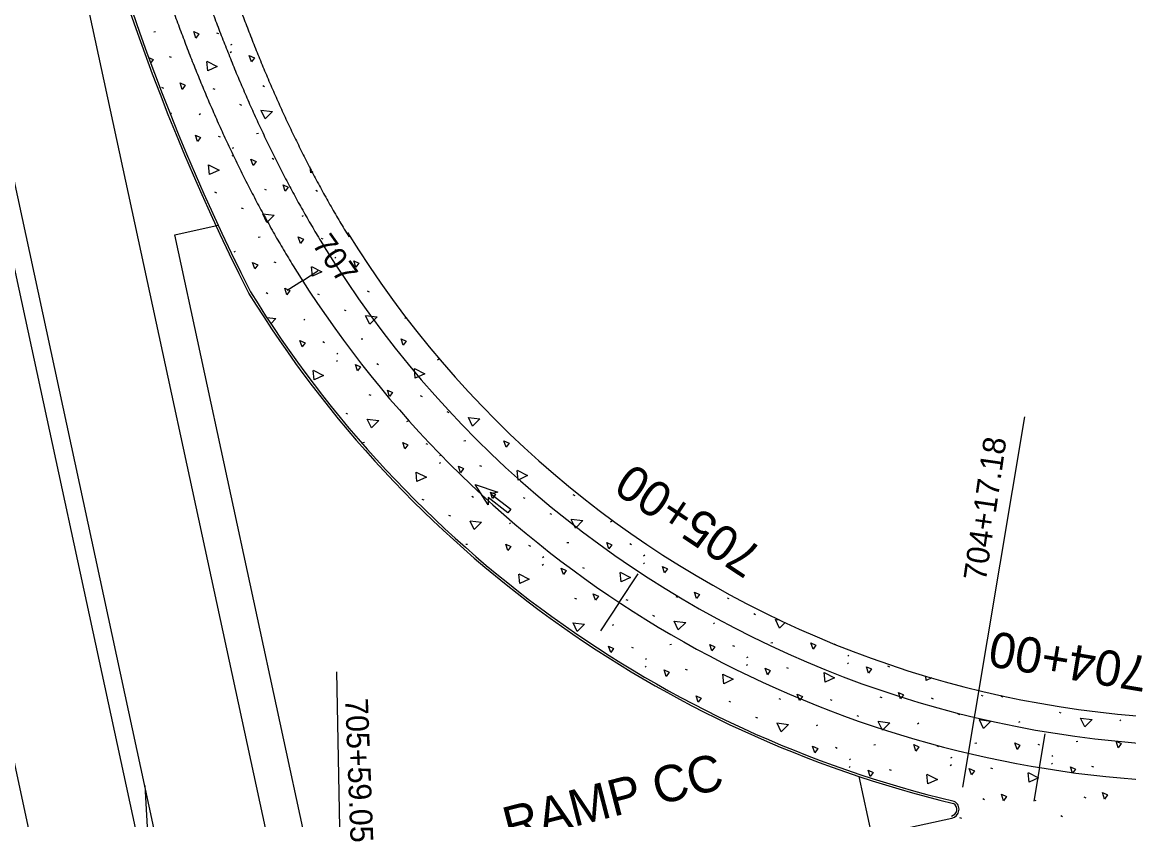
# Model space of a CAD drawing. Extents: x 0 to 1360, y 0 to 880.
# Drawn here: x 166 to 409.3, y 135 to 310.5 of the extents above; entities that cross this region are included whole.
import ezdxf

# ---------------------------------------------------------------- set-up
doc = ezdxf.new("R2010")
doc.units = 0
for name, color, linetype in [('Default', 7, 'Continuous'), ('PM_P_Cells', 7, 'Continuous'), ('PV_X_Curb', 7, 'Continuous'), ('RD_X_Concrete_Pad', 7, 'Continuous'), ('SH_Text', 7, 'Continuous')]:
    doc.layers.add(name, color=color, linetype=linetype)

# ---------------------------------------------------------------- blocks, each defined once
blk = doc.blocks.new('PMTHRP')
at = {"layer": 'PM_P_Cells'}
for p, q in [((-9.5, -0.5), (-9.5, 0.5)), ((-9.5, 0.5), (-4, 0.5)), ((-9.5, 0), (-9.5, 0)), ((-4, 0.5), (-5, 1.74)), ((-5, 1.74), (0, 0)), ((0, 0), (-5, -1.74)), ((0, 0), (0, 0)), ((-4, -0.5), (-9.5, -0.5)), ((-5, -1.74), (-4, -0.5))]:
    blk.add_line(p, q, dxfattribs=at)

msp = doc.modelspace()

# ---------------------------------------------------------------- linework, layer by layer
at = {"layer": 'Default'}
for p, q in [((243.77, 21.21), (123.28, 579.31)), ((219.22, 21.21), (123.28, 465.59)), ((215.13, 21.21), (123.28, 446.64)), ((195.36, 308.37), (194.96, 308.32)), ((208.78, 308.18), (209.18, 308.01)), ((212.11, 305.61), (211.85, 305.43)), ((198.38, 302.96), (198.79, 302.79)), ((212.04, 303.94), (211.77, 303.75)), ((196.67, 296.18), (197.08, 296.01)), ((207.96, 295.92), (208.36, 295.75)), ((218.91, 296.54), (219.31, 296.37)), ((213.83, 292.42), (214.23, 292.25)), ((205.21, 290.32), (204.94, 290.14)), ((209.15, 285.41), (209.55, 285.24)), ((217.97, 285.97), (217.57, 285.92)), ((212.48, 282.85), (212.22, 282.67)), ((212.41, 281.17), (212.15, 280.99)), ((220.99, 280.55), (221.39, 280.38)), ((208.33, 273.15), (208.73, 272.98)), ((219.28, 273.78), (219.68, 273.61)), ((230.57, 273.52), (230.97, 273.34)), ((214.2, 269.65), (214.6, 269.48)), ((227.81, 267.92), (227.55, 267.74)), ((199.59, 263.75), (209.14, 265.81)), ((231.46, 116.15), (199.59, 263.75)), ((218.34, 263.2), (217.94, 263.15)), ((231.76, 263.01), (232.16, 262.84)), ((235.09, 260.45), (234.83, 260.26)), ((212.85, 260.08), (212.59, 259.9)), ((212.78, 258.4), (212.69, 258.34)), ((235.02, 258.77), (234.75, 258.58)), ((221.36, 257.79), (221.77, 257.62)), ((225.61, 256.92), (225.61, 256.92)), ((227.67, 253.63), (231.04, 255.78)), ((227.67, 253.63), (224.29, 251.48)), ((219.65, 251.01), (220.06, 250.84)), ((230.94, 250.75), (231.34, 250.58)), ((241.89, 251.37), (242.29, 251.2)), ((236.81, 247.25), (237.21, 247.08)), ((228.19, 245.15), (227.92, 244.97)), ((250.41, 245.51), (250.16, 245.34)), ((232.13, 240.25), (232.53, 240.07)), ((240.95, 240.8), (240.55, 240.75)), ((235.39, 236), (235.13, 235.82)), ((235.46, 237.68), (235.2, 237.5)), ((257.63, 236.36), (257.36, 236.18)), ((243.97, 235.38), (244.37, 235.21)), ((242.26, 228.61), (242.66, 228.44)), ((253.55, 228.35), (253.95, 228.18)), ((237.18, 224.48), (237.58, 224.31)), ((259.42, 224.85), (259.82, 224.67)), ((250.79, 222.75), (250.53, 222.57)), ((372.82, 142.26), (386.4, 223.65)), ((241.32, 218.03), (240.92, 217.98)), ((254.74, 217.84), (255.14, 217.67)), ((263.56, 218.4), (263.16, 218.35)), ((258.07, 215.28), (257.81, 215.09)), ((258, 213.6), (257.73, 213.41)), ((266.58, 212.98), (266.98, 212.81)), ((253.92, 205.58), (254.32, 205.41)), ((264.87, 206.2), (265.27, 206.03)), ((276.15, 205.94), (276.56, 205.77)), ((287.11, 206.57), (287.51, 206.39)), ((259.79, 202.08), (260.19, 201.91)), ((282.02, 202.44), (282.43, 202.27)), ((273.4, 200.35), (273.14, 200.17)), ((295.64, 200.71), (295.38, 200.53)), ((263.93, 195.63), (263.53, 195.58)), ((277.35, 195.44), (277.75, 195.27)), ((286.17, 195.99), (285.77, 195.94)), ((299.58, 195.8), (299.99, 195.63)), ((280.68, 192.87), (280.42, 192.69)), ((302.92, 193.23), (302.65, 193.05)), ((280.61, 191.19), (280.34, 191.01)), ((289.19, 190.58), (289.59, 190.41)), ((302.84, 191.56), (302.58, 191.37)), ((155.32, 189.22), (171.25, 115.43)), ((297.28, 182.86), (301.42, 189.12)), ((287.48, 183.8), (287.88, 183.63)), ((297.28, 182.86), (293.15, 176.61)), ((298.76, 183.54), (299.17, 183.37)), ((309.72, 184.16), (310.12, 183.99)), ((321, 183.9), (321.4, 183.73)), ((304.63, 180.04), (305.04, 179.87)), ((326.87, 180.4), (327.27, 180.23)), ((282.8, 179.51), (282.8, 179.51)), ((296.01, 177.94), (295.75, 177.76)), ((318.25, 178.31), (317.99, 178.12)), ((299.96, 173.04), (300.36, 172.86)), ((308.77, 173.59), (308.38, 173.54)), ((322.19, 173.4), (322.6, 173.23)), ((331.01, 173.95), (330.61, 173.9)), ((344.43, 173.76), (344.83, 173.59)), ((303.29, 170.47), (303.03, 170.29)), ((325.53, 170.83), (325.26, 170.65)), ((347.76, 171.19), (347.5, 171.01)), ((303.22, 168.79), (302.95, 168.61)), ((311.8, 168.17), (312.2, 168)), ((325.45, 169.15), (325.19, 168.97)), ((334.04, 168.54), (334.44, 168.37)), ((347.69, 169.51), (347.43, 169.33)), ((356.27, 168.9), (356.68, 168.73)), ((236.63, 92.19), (235.19, 167.58)), ((321.37, 161.14), (321.77, 160.97)), ((332.33, 161.76), (332.73, 161.59)), ((343.61, 161.5), (344.01, 161.33)), ((354.56, 162.12), (354.97, 161.95)), ((365.85, 161.86), (366.25, 161.69)), ((376.8, 162.48), (377.2, 162.31)), ((371.72, 158.36), (372.12, 158.19)), ((393.96, 158.72), (394.36, 158.55)), ((327.24, 157.64), (327.64, 157.46)), ((340.86, 155.9), (340.6, 155.72)), ((349.48, 158), (349.88, 157.83)), ((363.1, 156.27), (362.83, 156.08)), ((385.33, 156.63), (385.07, 156.45)), ((407.57, 156.99), (407.31, 156.81)), ((389.66, 146.53), (390.9, 153.93)), ((344.8, 150.99), (345.2, 150.82)), ((353.62, 151.55), (353.22, 151.5)), ((367.04, 151.36), (367.44, 151.19)), ((375.86, 151.91), (375.46, 151.86)), ((389.28, 151.72), (389.68, 151.55)), ((398.1, 152.27), (397.7, 152.22)), ((348.14, 148.43), (347.87, 148.25)), ((370.37, 148.79), (370.11, 148.61)), ((392.61, 149.15), (392.35, 148.97)), ((348.06, 146.75), (347.8, 146.57)), ((356.64, 146.13), (357.05, 145.96)), ((370.3, 147.11), (370.04, 146.93)), ((378.88, 146.5), (379.29, 146.32)), ((389.66, 146.53), (388.43, 139.13)), ((392.54, 147.47), (392.27, 147.29)), ((401.12, 146.86), (401.52, 146.69)), ((352.85, 131.38), (350, 144.55)), ((193, 142.63), (195.85, 91.07)), ((377.17, 139.72), (377.57, 139.55)), ((388.46, 139.46), (388.86, 139.29)), ((399.41, 140.08), (399.81, 139.91)), ((372.09, 135.59), (372.49, 135.42)), ((394.33, 135.96), (394.73, 135.79))]:
    msp.add_line(p, q, dxfattribs=at)
for points in [[(203.76, 308.41), (204.88, 307.89), (204.22, 307), (203.76, 308.41)], [(193.82, 302.75), (194.84, 302.28), (194.28, 301.5)], [(206.66, 301.89), (208.94, 300.73), (206.87, 299.77), (206.66, 301.85)], [(215.96, 303.15), (217.08, 302.64), (216.43, 301.74), (215.96, 303.15)], [(200.77, 297.13), (201.89, 296.61), (201.23, 295.71), (200.77, 297.13)], [(198.51, 290.5), (198.85, 290.46), (198.62, 290.23)], [(218.54, 291.13), (221.08, 290.82), (219.47, 289.21), (218.56, 291.09)], [(204.13, 285.64), (205.25, 285.13), (204.59, 284.23), (204.13, 285.64)], [(216.33, 280.39), (217.45, 279.87), (216.8, 278.98), (216.33, 280.39)], [(207.03, 279.13), (209.32, 277.97), (207.24, 277), (207.03, 279.08)], [(229.93, 277.57), (229.48, 277.36), (229.35, 278.68)], [(223.38, 274.72), (224.49, 274.21), (223.84, 273.31), (223.38, 274.72)], [(218.91, 268.37), (221.45, 268.06), (219.84, 266.44), (218.93, 268.33)], [(226.74, 263.24), (227.86, 262.73), (227.2, 261.83), (226.74, 263.24)], [(238.94, 257.99), (240.06, 257.47), (239.41, 256.57), (238.94, 257.99)], [(216.7, 257.62), (217.82, 257.11), (217.17, 256.21), (216.7, 257.62)], [(229.64, 256.72), (231.92, 255.56), (229.85, 254.6), (229.64, 256.68)], [(223.75, 251.96), (224.86, 251.44), (224.21, 250.54), (223.75, 251.96)], [(241.52, 245.96), (244.06, 245.65), (242.45, 244.04), (241.54, 245.92)], [(219.8, 245.54), (221.82, 245.29), (220.7, 244.17)], [(249.35, 240.84), (250.46, 240.32), (249.81, 239.42), (249.35, 240.84)], [(227.11, 240.47), (228.23, 239.96), (227.57, 239.06), (227.11, 240.47)], [(230.01, 233.96), (232.3, 232.8), (230.22, 231.83), (230.01, 233.91)], [(239.31, 235.22), (240.43, 234.71), (239.78, 233.81), (239.31, 235.22)], [(252.25, 234.32), (254.53, 233.16), (252.46, 232.19), (252.25, 234.28)], [(246.35, 229.55), (247.47, 229.04), (246.82, 228.14), (246.35, 229.55)], [(241.89, 223.2), (244.43, 222.89), (242.82, 221.27), (241.91, 223.16)], [(264.13, 223.56), (266.67, 223.25), (265.06, 221.63), (264.14, 223.52)], [(249.72, 218.07), (250.83, 217.56), (250.18, 216.66), (249.72, 218.07)], [(271.95, 218.43), (273.07, 217.92), (272.42, 217.02), (271.95, 218.43)], [(261.92, 212.82), (263.04, 212.3), (262.39, 211.4), (261.92, 212.82)], [(274.86, 211.92), (277.14, 210.76), (275.07, 209.79), (274.86, 211.87)], [(252.62, 211.55), (254.9, 210.39), (252.83, 209.43), (252.62, 211.51)], [(268.96, 207.15), (270.08, 206.64), (269.43, 205.74), (268.96, 207.15)], [(264.5, 200.8), (267.04, 200.48), (265.43, 198.87), (264.52, 200.75)], [(286.74, 201.16), (289.28, 200.85), (287.66, 199.23), (286.75, 201.12)], [(272.32, 195.67), (273.44, 195.15), (272.79, 194.25), (272.32, 195.67)], [(294.56, 196.03), (295.68, 195.52), (295.03, 194.62), (294.56, 196.03)], [(284.53, 190.41), (285.65, 189.9), (285, 189), (284.53, 190.41)], [(306.77, 190.78), (307.89, 190.26), (307.23, 189.36), (306.77, 190.78)], [(275.23, 189.15), (277.51, 187.99), (275.44, 187.02), (275.23, 189.11)], [(297.47, 189.51), (299.75, 188.35), (297.68, 187.39), (297.47, 189.47)], [(313.81, 185.11), (314.93, 184.59), (314.28, 183.7), (313.81, 185.11)], [(291.57, 184.75), (292.69, 184.23), (292.04, 183.33), (291.57, 184.75)], [(287.11, 178.39), (289.65, 178.08), (288.04, 176.46), (287.12, 178.35)], [(309.35, 178.75), (311.89, 178.44), (310.27, 176.83), (309.36, 178.71)], [(331.58, 179.12), (332.55, 179)], [(333.75, 178.43), (332.51, 177.19), (331.6, 179.08)], [(294.93, 173.26), (296.05, 172.75), (295.4, 171.85), (294.93, 173.26)], [(317.17, 173.63), (318.29, 173.11), (317.64, 172.21), (317.17, 173.63)], [(339.41, 173.99), (340.53, 173.47), (339.88, 172.58), (339.41, 173.99)], [(307.14, 168.01), (308.26, 167.5), (307.61, 166.6), (307.14, 168.01)], [(329.38, 168.37), (330.49, 167.86), (329.84, 166.96), (329.38, 168.37)], [(351.61, 168.73), (352.73, 168.22), (352.08, 167.32), (351.61, 168.73)], [(320.08, 167.11), (322.36, 165.95), (320.29, 164.98), (320.08, 167.07)], [(342.31, 167.47), (344.6, 166.31), (342.53, 165.34), (342.31, 167.43)], [(365.98, 166.28), (364.76, 165.71), (364.67, 166.66)], [(358.66, 163.07), (359.78, 162.55), (359.12, 161.65), (358.66, 163.07)], [(314.18, 162.34), (315.3, 161.83), (314.65, 160.93), (314.18, 162.34)], [(336.42, 162.71), (337.54, 162.19), (336.89, 161.29), (336.42, 162.71)], [(381.58, 162.32), (381.36, 162.02), (381.24, 162.4)], [(331.95, 156.35), (334.5, 156.04), (332.88, 154.42), (331.97, 156.31)], [(354.19, 156.71), (356.74, 156.4), (355.12, 154.79), (354.21, 156.67)], [(376.43, 157.08), (378.97, 156.76), (377.36, 155.15), (376.45, 157.03)], [(398.67, 157.44), (401.21, 157.13), (399.6, 155.51), (398.68, 157.4)], [(339.78, 151.22), (340.9, 150.71), (340.25, 149.81), (339.78, 151.22)], [(362.02, 151.59), (363.14, 151.07), (362.49, 150.17), (362.02, 151.59)], [(384.26, 151.95), (385.37, 151.43), (384.72, 150.53), (384.26, 151.95)], [(406.49, 152.31), (407.61, 151.8), (406.96, 150.9), (406.49, 152.31)], [(351.98, 145.97), (353.1, 145.45), (352.45, 144.56), (351.98, 145.97)], [(374.22, 146.33), (375.34, 145.82), (374.69, 144.92), (374.22, 146.33)], [(396.46, 146.69), (397.58, 146.18), (396.93, 145.28), (396.46, 146.69)], [(364.92, 145.07), (367.21, 143.91), (365.13, 142.94), (364.92, 145.02)], [(387.16, 145.43), (389.44, 144.27), (387.37, 143.3), (387.16, 145.39)], [(381.27, 140.66), (382.38, 140.15), (381.73, 139.25), (381.27, 140.66)], [(403.5, 141.03), (404.62, 140.51), (403.97, 139.61), (403.5, 141.03)]]:
    msp.add_lwpolyline(points, dxfattribs=at)
for centre, radius, start, end in [((650.45, 470.48), 486.96, 188.7836, 206.7998), ((650.45, 470.48), 486.46, 188.7836, 206.7998), ((428.95, 382.01), 230.73, 211.5995, 282.1946), ((428.95, 382.01), 238.73, 211.5995, 311.7475), ((428.95, 382.01), 249.73, 211.5995, 256.5653), ((369.97, 137.35), 2, 282.183, 61.6447)]:
    msp.add_arc(centre, radius, start, end, dxfattribs=at)
for points in [[(183.3, 399.49), (183.78, 397.52), (184.25, 395.55), (184.73, 393.59), (185.21, 391.62), (185.69, 389.65), (186.17, 387.69), (186.65, 385.73), (187.13, 383.76), (187.61, 381.8), (188.09, 379.84), (188.58, 377.89), (189.07, 375.93), (189.56, 373.98), (190.06, 372.02), (190.55, 370.07), (191.05, 368.12), (191.56, 366.17), (192.06, 364.23), (192.57, 362.28), (193.09, 360.34), (193.61, 358.4), (194.13, 356.46), (194.66, 354.53), (195.19, 352.59), (195.73, 350.66), (196.28, 348.74), (196.82, 346.81), (197.38, 344.89), (197.94, 342.97), (198.51, 341.05), (199.08, 339.13), (199.66, 337.22), (200.24, 335.31), (200.84, 333.4), (201.44, 331.5), (202.05, 329.6), (202.66, 327.71), (203.28, 325.81), (203.92, 323.92), (204.56, 322.04), (205.2, 320.16), (205.86, 318.28), (206.52, 316.41), (207.2, 314.54), (207.88, 312.67), (208.57, 310.81), (209.27, 308.95), (209.99, 307.1), (210.71, 305.26), (211.44, 303.42), (212.18, 301.58), (212.93, 299.75), (213.69, 297.92), (214.47, 296.1), (215.25, 294.29), (216.05, 292.48), (216.85, 290.67), (217.67, 288.88), (218.5, 287.09), (219.34, 285.3), (220.19, 283.52), (221.06, 281.75), (221.93, 279.99), (222.82, 278.23), (223.73, 276.48), (224.64, 274.74), (225.57, 273.01), (226.51, 271.28), (227.46, 269.57), (228.43, 267.86), (229.41, 266.16), (230.4, 264.46), (231.4, 262.78), (232.44, 261.08)], [(175.53, 397.61), (176, 395.64), (176.48, 393.67), (176.96, 391.7), (177.43, 389.73), (177.91, 387.76), (178.39, 385.79), (178.88, 383.82), (179.36, 381.85), (179.84, 379.89), (180.33, 377.92), (180.82, 375.95), (181.31, 373.99), (181.8, 372.02), (182.3, 370.05), (182.8, 368.09), (183.31, 366.13), (183.81, 364.16), (184.32, 362.2), (184.84, 360.24), (185.36, 358.28), (185.88, 356.32), (186.41, 354.37), (186.95, 352.41), (187.48, 350.46), (188.03, 348.51), (188.58, 346.55), (189.13, 344.6), (189.7, 342.66), (190.26, 340.71), (190.84, 338.77), (191.42, 336.83), (192.01, 334.89), (192.6, 332.95), (193.2, 331.01), (193.81, 329.08), (194.43, 327.15), (195.06, 325.22), (195.69, 323.3), (196.33, 321.37), (196.98, 319.45), (197.64, 317.54), (198.31, 315.62), (198.99, 313.71), (199.68, 311.81), (200.38, 309.9), (201.08, 308), (201.8, 306.11), (202.53, 304.21), (203.26, 302.33), (204.01, 300.44), (204.77, 298.56), (205.54, 296.69), (206.32, 294.82), (207.11, 292.95), (207.92, 291.09), (208.73, 289.23), (209.56, 287.38), (210.4, 285.54), (211.25, 283.7), (212.11, 281.87), (212.99, 280.04), (213.88, 278.22), (214.78, 276.4), (215.7, 274.59), (216.63, 272.79), (217.57, 271), (218.53, 269.21), (219.5, 267.43), (220.48, 265.66), (221.48, 263.89), (222.49, 262.14), (223.51, 260.39), (224.55, 258.65), (225.61, 256.92)], [(407.38, 129.06), (432.62, 134.58), (456.13, 140.1), (479.83, 146.42), (503.62, 153.93), (526.94, 163.59), (549.22, 175.79)]]:
    msp.add_spline(points, degree=3, dxfattribs=at)
at = {"layer": 'PV_X_Curb'}
for centre, radius, start, end in [((650.45, 470.48), 486.46, 188.7836, 206.7998), ((428.95, 382.01), 250.23, 211.5995, 256.5492), ((428.95, 382.01), 249.73, 211.5995, 256.5653), ((369.97, 137.35), 2, 282.183, 61.6447), ((369.97, 137.35), 1.5, 282.183, 59.3214)]:
    msp.add_arc(centre, radius, start, end, dxfattribs=at)
at = {"layer": 'RD_X_Concrete_Pad'}
msp.add_line((250.29, 109.46), (370.4, 135.39), dxfattribs=at)
msp.add_arc((428.98, 381.96), 224.73, 211.5995, 282.1741, dxfattribs=at)
msp.add_spline([(209.84, 325.12), (209.91, 324.93), (210.54, 323.07), (211.18, 321.21), (211.83, 319.36), (212.48, 317.52), (213.14, 315.67), (213.82, 313.84), (214.5, 312.01), (215.19, 310.18), (215.89, 308.36), (216.6, 306.54), (217.32, 304.73), (218.04, 302.93), (218.78, 301.13), (219.53, 299.34), (220.29, 297.55), (221.06, 295.77), (221.84, 294), (222.63, 292.23), (223.43, 290.47), (224.24, 288.71), (225.07, 286.97), (225.9, 285.23), (226.75, 283.49), (227.6, 281.77), (228.47, 280.05), (229.36, 278.34), (230.25, 276.64), (231.15, 274.95), (232.07, 273.26), (233, 271.59), (233.94, 269.92), (234.9, 268.26), (235.87, 266.61), (236.85, 264.97), (237.87, 263.29)], degree=3, dxfattribs=at)

# ---------------------------------------------------------------- block references
at = {"layer": 'SH_Text', "rotation": 142.08010713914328}
msp.add_blockref('PMTHRP', (265.62, 208.81), dxfattribs=at)

# ---------------------------------------------------------------- texts
at = {"layer": 'Default'}
for s, height, rotation, p in [('707', 5, 305.3118, (229.63, 261.63)), ('704+17.18', 5, 81.7228, (377.86, 187.4)), ('705+00', 7.8, 146.5292, (329.26, 194.4)), ('704+00', 7.8, 170.5292, (413.99, 170.83)), ('705+59.05', 5, 272.1772, (237.04, 161.71)), ('RAMP CC', 8, 14.4739, (272.96, 129.77))]:
    msp.add_text(s, height=height, rotation=rotation, dxfattribs=at).set_placement(p)

doc.saveas('drawing.dxf')
